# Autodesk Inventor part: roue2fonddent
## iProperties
Shininess: 64.0
Length Units: 11269
Angle Units: 11279
Time Units: 11290
Mass Units: 11283
Length Display Precision: 3
Angle Display Precision: 2
Compacted: True
Part Number: roue2fonddent
Document SubType Name: Modeling
Created: 2004-09
Material: Par défaut
Designer: Administrateur
Density: 1 g/cm^3
Density: 0.0
Volumn: 0.0
Area: 0.0
PropertySet Name: Model Information
Control State: 0
Master: False
Checked Out: False
Author: Administrateur
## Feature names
1. Extrusion1
